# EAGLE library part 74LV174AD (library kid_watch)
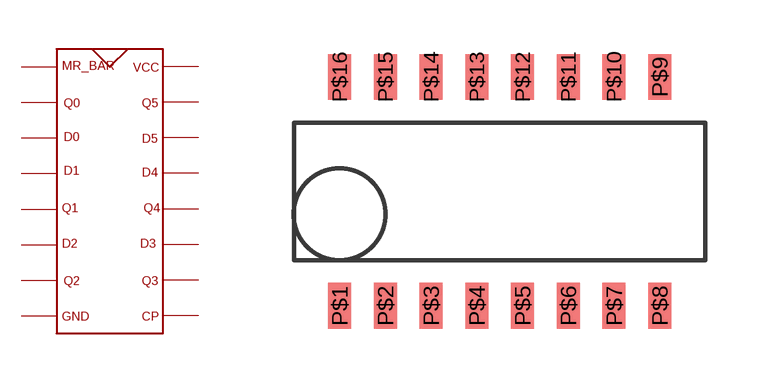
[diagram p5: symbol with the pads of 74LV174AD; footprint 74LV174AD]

Designator prefix -

## 74LV174AD  [74LV174AD]
P$1  P$1
P$2  P$2
P$3  P$3
P$4  P$4
P$5  P$5
P$6  P$6
P$7  P$7
P$8  P$8
P$9  P$9
P$10  P$10
P$11  P$11
P$12  P$12
P$13  P$13
P$14  P$14
P$15  P$15
P$16  P$16

## Footprint 74LV174AD (pad centres in mm)
smd 0.635 x 1.27: P$1 0,0; P$2 1.27,0; P$3 2.54,0; P$4 3.81,0; P$5 5.08,0; P$6 6.35,0; P$7 7.62,0; P$8 8.89,0; P$9 8.89,6.35; P$10 7.62,6.35; P$11 6.35,6.35; P$12 5.08,6.35; P$13 3.81,6.35; P$14 2.54,6.35; P$15 1.27,6.35; P$16 0,6.35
